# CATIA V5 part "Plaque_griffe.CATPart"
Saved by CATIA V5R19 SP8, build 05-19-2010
Part number: Plaque griffe
Bounding box of the stored display mesh (mm): x -48.736 to -15.5, y -26 to 26, z -1.25 to 1.25
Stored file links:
  C:\Users\ThinkMotion\Desktop\EU_thinkMotion\iao\IAO_MMS_Groupe3\ecartoux\projet_IAO_ecartoux\projet_IAO_ecartoux\griffe_d'une_camera_ecartoux\Plaque_griffe.CATPart
  C:\Users\ThinkMotion\Desktop\EU_thinkMotion\iao\IAO_MMS_Groupe3\ecartoux\projet_IAO_ecartoux\projet_IAO_ecartoux\griffe_d'une_camera_ecartoux\Mecanisme_a_coulisse_et_leviers_de_la_griffe_d'un_camera_ecartoux.CATProduct
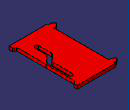
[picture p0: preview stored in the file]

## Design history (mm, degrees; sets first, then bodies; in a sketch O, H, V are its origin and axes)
External parameters (linked from other documents)
  External.a = 5.5 mm
Set1
  Plane1: linked copy from another document
  Line1: linked copy from another document
  Line2: linked copy from another document
  Point1: linked copy from another document
  Line3: linked copy from another document
  Point2: linked copy from another document
  Sketch1, origin (0, 0, 0), H (1, 0, 0), V (0, 1, 0), geometry linked from another document
Body1 (main body)
  Sketch2 on Plane1, origin (0, 0, 0), H (1, 0, 0), V (0, 1, 0)
    point P1 (-44.5, 26)
    line L1 (-44.5, 26) -> (-15.5, 26)
    line L2 (-15.5, 26) -> (-15.5, 23.5)
    line L3 (-44.5, 0) -> (-44.5, 21)
    point P2 (-15.5, 26)
    point P3 (-44.5, 0)
    reference projected line E1 (-43, 26) -> (-14, 26) from Line1
    line L4 (-17.5, 0) -> (-17.5, 22.0189)
    point P4 (-17.5, 0)
    point P5 (-17.5, 22.0189)
    line L5 (-15.5, 23.5) -> (-17.4095, 22.3975)
    point P6 (-15.5, 23.5)
    point P7 (-17.4095, 22.3975)
    reference projected line E4 (-43, 26) -> (-14, 26) from Line3
    arc A1 centre (-16.6623, 22.0189) radius 0.8377 from (-17.5, 22.0189) to (-17.4095, 22.3975) cw
    line L6 (-44.5, 25) -> (-46.5, 25)
    point P9 (-44.5, 25)
    point P10 (-46.5, 25)
    line L7 (-44.5, 21) -> (-46.5, 21)
    point P11 (-44.5, 21)
    point P12 (-46.5, 21)
    line L8 (-48.7361, 23) -> (-46.5, 21)
    point P13 (-48.7361, 23)
    point P14 (-46.5, 21)
    line L9 (-48.7361, 23) -> (-46.5, 25)
    point P15 (-46.5, 25)
    line L10 (-44.5, 25) -> (-44.5, 26)
    construction line L11 (-61.2815, 0) -> (1.4807, 0)
    point P16 (-61.2815, 0)
    point P18 (-44.5, -26)
    point P19 (-15.5, -26)
    point P20 (-44.5, 0)
    point P21 (-17.5, 0)
    point P22 (-17.5, -22.0189)
    point P23 (-15.5, -23.5)
    point P24 (-17.4095, -22.3975)
    point P26 (-44.5, -25)
    point P27 (-46.5, -25)
    point P28 (-44.5, -21)
    point P29 (-46.5, -21)
    point P30 (-48.7361, -23)
    point P31 (-46.5, -21)
    point P32 (-46.5, -25)
    line L12 (-44.5, -26) -> (-15.5, -26)
    line L13 (-15.5, -26) -> (-15.5, -23.5)
    line L14 (-44.5, 0) -> (-44.5, -21)
    line L15 (-17.5, 0) -> (-17.5, -22.0189)
    line L16 (-15.5, -23.5) -> (-17.4095, -22.3975)
    arc A2 centre (-16.6623, -22.0189) radius 0.8377 from (-17.5, -22.0189) to (-17.4095, -22.3975) ccw
    line L17 (-44.5, -25) -> (-46.5, -25)
    line L18 (-44.5, -21) -> (-46.5, -21)
    line L19 (-48.7361, -23) -> (-46.5, -21)
    line L20 (-48.7361, -23) -> (-46.5, -25)
    line L21 (-44.5, -25) -> (-44.5, -26)
    line L22 (-18.5, 0) -> (-18.5, 16.5)
    point P33 (-18.5, 0)
    line L23 (-21.5, 1.3271) -> (-21.5, 16.5)
    arc A3 centre (-20, 16.5) radius 1.5 from (-18.5, 16.5) to (-21.5, 16.5) ccw
    point P36 (-20, 16.5)
    line L24 (-24, -6.3271) -> (-24, -15)
    point P38 (-24, -15)
    line L25 (-27, -5) -> (-27, -15)
    point P40 (-27, -15)
    arc A4 centre (-25.5, -15) radius 1.5 from (-27, -15) to (-24, -15) ccw
    point P41 (-25.5, -15)
    arc A5 centre (-20, 0) radius 1.5 from (-18.991, -1.1099) to (-18.5, 0) ccw
    arc A6 centre (-23, 1.3271) radius 1.5 from (-21.991, 0.2172) to (-21.5, 1.3271) ccw
    arc A7 centre (-22.5, -6.3271) radius 1.5 from (-23.509, -5.2172) to (-24, -6.3271) ccw
    line L26 (-21.991, 0.2172) -> (-26.509, -3.8901)
    arc A8 centre (-25.5, -5) radius 1.5 from (-26.509, -3.8901) to (-27, -5) ccw
    point P48 (-27, -15)
    point P49 (-24, -15)
    line L27 (-18.991, -1.1099) -> (-23.509, -5.2172)
    point P52 (-18.5, 0)
    construction line L28 (-20, 23.0933) -> (-20, -30.0153)
    reference projected point E5 (-20, 14) from Point2
    axis line L29 (-25.5, -9.8707) -> (-25.5, -28.2636)
    distance L2 L3 = 29
    angle L2 L5 = 60
    distance P6 E4 = 2.5
    distance L6 L7 = 4
    length L7 = 2
    length L6 = 2
    length L9 = 3
    length L8 = 3
    distance L7 L1 = 5
    distance L23 L22 = 3
    radius A3 = 1.5
    distance P36 L11 = 16.5
    distance L25 L24 = 3
    radius A4 = 1.5
    distance P41 L11 = 15
    radius A5 = 1.5
    radius A6 = 1.5
    length L25 = 10
    distance L26 L27 = 3
    radius A6 = 1.5 (reference)
    radius A8 = 1.5
    radius A7 = 1.5
    radius A1 = 0.8377
    distance L4 L2 = 2
    length L5 = 2.2049
    distance L24 L15 = 6.5
    distance L29 L28 = 5.5 {= External.a}
    distance L29 L24 = 1.5
    distance L22 L28 = 1.5
    horizontal: L1 H, L6 H, L7 H, L11 H
    vertical: L2 V, L3 V, L4 V, L10 V, L22 V, L23 V, L24 V, L25 V, L28 V, L29 V
    coincidence: E1 L1, P9 L3, P14 P12, P10 P15, L3 L10, P16 H, P33 L11, P40 A4, P38 A4, L24 P49, L25 P48, P52 P33, P4 L11, P3 L11, E5 L28
    tangency: A1 L4, A3 L22, A4 L24, L22 A5, L23 A6, A7 L24, L26 A6, A8 L25, A7 L27, A5 L27, L26 A8
    symmetry: P1 P18 L11, P2 P19 L11, P3 P20 L11, P4 P21 L11, P5 P22 L11, P6 P23 L11, P7 P24 L11, P9 P26 L11, P10 P27 L11, P11 P28 L11, P12 P29 L11, P13 P30 L11, P14 P31 L11, P15 P32 L11, L1 L12 L11, L2 L13 L11, L3 L14 L11, L4 L15 L11, L5 L16 L11, A1 A2 L11, L6 L17 L11, L7 L18 L11, L8 L19 L11, L9 L20 L11, L10 L21 L11
  Pad1: profile Sketch2, direction (0, 0, 1), length 1.25, mirrored extent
